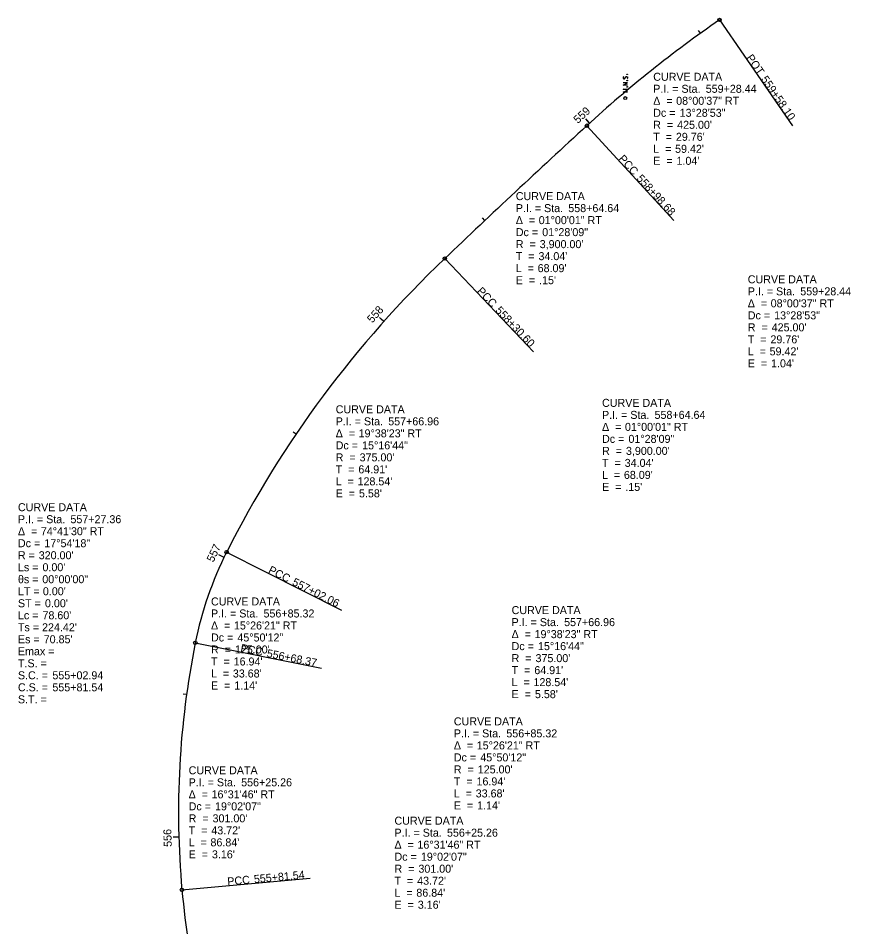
# Model space of a CAD drawing. Extents: x 1922787 to 1923078, y 359089 to 360354.
# Drawn here: x 1922786.9 to 1923078.3, y 360035.7 to 360353.5 of the extents above; entities that cross this region are included whole.
import ezdxf

# ---------------------------------------------------------------- set-up
doc = ezdxf.new("R2010")
doc.units = 0
for name, color, linetype in [('GE_P_Alignment', 7, 'Continuous'), ('GE_P_Alignment_1000_Curve_Data', 7, 'Continuous'), ('GE_P_Alignment_1000_Stations', 7, 'Continuous'), ('GE_P_Alignment_100_Curve_Data', 7, 'Continuous'), ('GE_P_Alignment_100_Stations', 7, 'Continuous'), ('GE_P_Alignment_500_Curve_Data', 7, 'Continuous'), ('GE_P_Alignment_500_Stations', 7, 'Continuous'), ('SV_P_Control_Cells_Set', 7, 'Continuous')]:
    doc.layers.add(name, color=color, linetype=linetype)

msp = doc.modelspace()

# ---------------------------------------------------------------- linework, layer by layer
at = {"layer": 'GE_P_Alignment'}
for centre, radius, start, end in [((1923273.39, 360002.89), 425, 124.5553, 132.5656), ((1925624, 357443.54), 3900, 132.56556, 133.56583), ((1923194.61, 359997.69), 375, 133.5658, 153.2056), ((1922971.45, 360110.39), 125, 153.2056, 168.6447), ((1923144.01, 360075.74), 301, 168.6447, 185.1742), ((1923162.93, 360077.45), 320, 185.1742, 199.2469)]:
    msp.add_arc(centre, radius, start, end, dxfattribs=at)
at = {"layer": 'GE_P_Alignment_1000_Stations'}
for p, q in [((1923032.33, 360352.91), (1923057.86, 360315.85)), ((1922985.91, 360315.9), (1923016.35, 360282.76)), ((1922936.17, 360269.41), (1922967.18, 360236.81)), ((1922859.87, 360166.74), (1922900.04, 360146.45)), ((1922848.9, 360135), (1922893.02, 360126.14)), ((1922844.24, 360048.59), (1922889.05, 360052.65))]:
    msp.add_line(p, q, dxfattribs=at)
for centre in [(1923032.33, 360352.91), (1922985.91, 360315.9), (1922936.17, 360269.41), (1922859.87, 360166.74), (1922848.9, 360135), (1922844.24, 360048.59)]:
    msp.add_circle(centre, 0.6, dxfattribs=at)
at = {"layer": 'GE_P_Alignment_100_Stations'}
for p, q in [((1923032.33, 360352.91), (1923057.86, 360315.85)), ((1923025.7, 360348.25), (1923025, 360349.23)), ((1922986.88, 360316.79), (1922985.53, 360318.27)), ((1922985.91, 360315.9), (1923016.35, 360282.76)), ((1922950.26, 360282.75), (1922949.44, 360283.62)), ((1922936.17, 360269.41), (1922967.18, 360236.81)), ((1922914.88, 360247.44), (1922913.39, 360248.78)), ((1922884.16, 360208.04), (1922883.17, 360208.71)), ((1922858.96, 360164.9), (1922857.16, 360165.77)), ((1922859.87, 360166.74), (1922900.04, 360146.45)), ((1922848.9, 360135), (1922893.02, 360126.14)), ((1922845.83, 360116.89), (1922844.65, 360117.05)), ((1922843.13, 360067.02), (1922841.14, 360066.96)), ((1922844.24, 360048.59), (1922889.05, 360052.65))]:
    msp.add_line(p, q, dxfattribs=at)
for centre in [(1923032.33, 360352.91), (1922985.91, 360315.9), (1922936.17, 360269.41), (1922859.87, 360166.74), (1922848.9, 360135), (1922844.24, 360048.59)]:
    msp.add_circle(centre, 0.6, dxfattribs=at)
at = {"layer": 'GE_P_Alignment_500_Stations'}
for p, q in [((1923032.33, 360352.91), (1923057.86, 360315.85)), ((1922986.88, 360316.79), (1922986.07, 360317.68)), ((1922985.91, 360315.9), (1923016.35, 360282.76)), ((1922936.17, 360269.41), (1922967.18, 360236.81)), ((1922914.88, 360247.44), (1922913.98, 360248.24)), ((1922858.96, 360164.9), (1922857.88, 360165.42)), ((1922859.87, 360166.74), (1922900.04, 360146.45)), ((1922848.9, 360135), (1922893.02, 360126.14)), ((1922843.13, 360067.02), (1922841.94, 360066.99)), ((1922844.24, 360048.59), (1922889.05, 360052.65))]:
    msp.add_line(p, q, dxfattribs=at)
for centre in [(1923032.33, 360352.91), (1922985.91, 360315.9), (1922936.17, 360269.41), (1922859.87, 360166.74), (1922848.9, 360135), (1922844.24, 360048.59)]:
    msp.add_circle(centre, 0.6, dxfattribs=at)
at = {"layer": 'SV_P_Control_Cells_Set'}
for points in [[(1922998.67, 360333.01), (1922998.64, 360332.99), (1922998.62, 360332.96), (1922998.58, 360332.86), (1922998.55, 360332.74), (1922998.55, 360332.65), (1922998.55, 360332.61), (1922998.59, 360332.47), (1922998.67, 360332.35), (1922998.77, 360332.27), (1922998.87, 360332.25), (1922998.94, 360332.25), (1922999.04, 360332.27), (1922999.13, 360332.36), (1922999.51, 360332.97), (1922999.56, 360333.02), (1922999.61, 360333.04), (1922999.69, 360333.07), (1922999.76, 360333.07), (1922999.84, 360333.06), (1922999.89, 360333.04), (1922999.95, 360333.02), (1923000, 360333), (1923000.04, 360332.98), (1923000.08, 360332.95), (1923000.1, 360332.91), (1923000.13, 360332.87), (1923000.14, 360332.84), (1923000.15, 360332.74), (1923000.15, 360332.58), (1923000.13, 360332.48), (1923000.04, 360332.34), (1922999.96, 360332.25)], [(1922999.94, 360333.83), (1922999.94, 360333.88), (1922999.96, 360333.92), (1923000.01, 360333.95), (1923000.08, 360333.95), (1923000.13, 360333.92), (1923000.15, 360333.88), (1923000.15, 360333.83), (1923000.13, 360333.79), (1923000.08, 360333.76), (1923000.01, 360333.76), (1922999.96, 360333.79), (1922999.94, 360333.83)], [(1923000.15, 360330.04), (1922998.55, 360330.04), (1923000.15, 360330.86), (1922998.55, 360330.86)], [(1922999.94, 360331.64), (1922999.94, 360331.7), (1922999.96, 360331.73), (1923000.01, 360331.77), (1923000.08, 360331.77), (1923000.13, 360331.73), (1923000.15, 360331.7), (1923000.15, 360331.64), (1923000.13, 360331.61), (1923000.08, 360331.58), (1923000.01, 360331.58), (1922999.96, 360331.61), (1922999.94, 360331.64)], [(1922999.94, 360329.43), (1922999.94, 360329.48), (1922999.96, 360329.52), (1923000.01, 360329.55), (1923000.08, 360329.55), (1923000.13, 360329.52), (1923000.15, 360329.48), (1923000.15, 360329.43), (1923000.13, 360329.4), (1923000.08, 360329.36), (1923000.01, 360329.36), (1922999.96, 360329.4), (1922999.94, 360329.43)], [(1923000.15, 360327.67), (1922998.55, 360327.67), (1923000.15, 360328.17), (1922998.55, 360328.66), (1923000.15, 360328.66)]]:
    msp.add_lwpolyline(points, dxfattribs=at)
msp.add_circle((1922999.35, 360325.58), 0.497, dxfattribs=at)

# ---------------------------------------------------------------- texts
at = {"layer": 'GE_P_Alignment_1000_Curve_Data'}
for s, p in [('CURVE DATA', (1923009.12, 360331.61)), ('P.I. = Sta. ', (1923009.12, 360327.41)), ('559+28.44', (1923027.49, 360327.41)), ('Δ  = ', (1923009.12, 360323.21)), ('08°00\'37" RT', (1923017.14, 360323.21)), ('Dc = ', (1923009.12, 360319.01)), ('13°28\'53"', (1923018.36, 360319.01)), ('R  = ', (1923009.12, 360314.81)), ("425.00'", (1923017.49, 360314.81)), ('T  = ', (1923009.12, 360310.61)), ("29.76'", (1923017.05, 360310.61)), ('L  = ', (1923009.12, 360306.41)), ("59.42'", (1923016.77, 360306.41)), ('E  = ', (1923009.12, 360302.21)), ("1.04'", (1923017.27, 360302.21)), ('CURVE DATA', (1922961.04, 360289.86)), ('P.I. = Sta. ', (1922961.04, 360285.66)), ('558+64.64', (1922979.41, 360285.66)), ('Δ  = ', (1922961.04, 360281.46)), ('01°00\'01" RT', (1922969.06, 360281.46)), ('Dc = ', (1922961.04, 360277.26)), ('01°28\'09"', (1922970.28, 360277.26)), ('R  = ', (1922961.04, 360273.06)), ("3,900.00'", (1922969.4, 360273.06)), ('T  = ', (1922961.04, 360268.86)), ("34.04'", (1922968.97, 360268.86)), ('L  = ', (1922961.04, 360264.66)), ("68.09'", (1922968.68, 360264.66)), ('E  = ', (1922961.04, 360260.46)), (".15'", (1922969.19, 360260.46)), ('CURVE DATA', (1922898.02, 360215.28)), ('P.I. = Sta. ', (1922898.02, 360211.08)), ('557+66.96', (1922916.39, 360211.08)), ('Δ  = ', (1922898.02, 360206.88)), ('19°38\'23" RT', (1922906.04, 360206.88)), ('Dc = ', (1922898.02, 360202.68)), ('15°16\'44"', (1922907.26, 360202.68)), ('R  = ', (1922898.02, 360198.48)), ("375.00'", (1922906.39, 360198.48)), ('T  = ', (1922898.02, 360194.28)), ("64.91'", (1922905.95, 360194.28)), ('L  = ', (1922898.02, 360190.08)), ("128.54'", (1922905.67, 360190.08)), ('E  = ', (1922898.02, 360185.88)), ("5.58'", (1922906.17, 360185.88)), ('CURVE DATA', (1922786.84, 360181.04)), ('P.I. = Sta. ', (1922786.84, 360176.84)), ('557+27.36', (1922805.21, 360176.84)), ('Δ  = ', (1922786.84, 360172.64)), ('74°41\'30" RT', (1922794.86, 360172.64)), ('Dc = ', (1922786.84, 360168.44)), ('17°54\'18"', (1922796.08, 360168.44)), ('R = ', (1922786.84, 360164.24)), ("320.00'", (1922794.12, 360164.24)), ('Ls = ', (1922786.84, 360160.04)), ("0.00'", (1922795.43, 360160.04)), ('θs = ', (1922786.84, 360155.84)), ('00°00\'00"', (1922795.37, 360155.84)), ('LT = ', (1922786.84, 360151.64)), ("0.00'", (1922795.57, 360151.64)), ('ST = ', (1922786.84, 360147.44)), ("0.00'", (1922796.3, 360147.44)), ('CURVE DATA', (1922854.39, 360148.07)), ('Lc = ', (1922786.84, 360143.24)), ("78.60'", (1922795.43, 360143.24)), ('P.I. = Sta. ', (1922854.39, 360143.87)), ('556+85.32', (1922872.76, 360143.87)), ('Ts = ', (1922786.84, 360139.04)), ("224.42'", (1922795.28, 360139.04)), ('Δ  = ', (1922854.39, 360139.67)), ('15°26\'21" RT', (1922862.41, 360139.67)), ('Es = ', (1922786.84, 360134.84)), ("70.85'", (1922795.86, 360134.84)), ('Dc = ', (1922854.39, 360135.47)), ('45°50\'12"', (1922863.63, 360135.47)), ('Emax = ', (1922786.84, 360130.64)), ('R  = ', (1922854.39, 360131.27)), ("125.00'", (1922862.76, 360131.27)), ('T.S. = ', (1922786.84, 360126.44)), ('T  = ', (1922854.39, 360127.07)), ("16.94'", (1922862.32, 360127.07)), ("33.68'", (1922862.03, 360122.87)), ('S.C. = ', (1922786.84, 360122.24)), ('555+02.94', (1922798.9, 360122.24)), ('L  = ', (1922854.39, 360122.87)), ('C.S. = ', (1922786.84, 360118.04)), ('555+81.54', (1922798.9, 360118.04)), ('E  = ', (1922854.39, 360118.67)), ("1.14'", (1922862.54, 360118.67)), ('S.T. = ', (1922786.84, 360113.84)), ('CURVE DATA', (1922846.57, 360089)), ('P.I. = Sta. ', (1922846.57, 360084.8)), ('556+25.26', (1922864.94, 360084.8)), ('Δ  = ', (1922846.57, 360080.6)), ('16°31\'46" RT', (1922854.59, 360080.6)), ('Dc = ', (1922846.57, 360076.4)), ('19°02\'07"', (1922855.81, 360076.4)), ('R  = ', (1922846.57, 360072.2)), ("301.00'", (1922854.94, 360072.2)), ('T  = ', (1922846.57, 360068)), ("43.72'", (1922854.5, 360068)), ('L  = ', (1922846.57, 360063.8)), ("86.84'", (1922854.21, 360063.8)), ('E  = ', (1922846.57, 360059.6)), ("3.16'", (1922854.72, 360059.6))]:
    msp.add_text(s, height=2.8, dxfattribs=at).set_placement(p)
at = {"layer": 'GE_P_Alignment_1000_Stations'}
for s, rotation, p in [('POT', 304.5553, (1923041.51, 360339.66)), ('559+58.10', 304.5553, (1923046.69, 360332.14)), ('PCC', 312.5656, (1922996.77, 360304.14)), ('558+98.68', 312.5656, (1923003.1, 360297.26)), ('PCC', 313.5658, (1922947.23, 360257.84)), ('558+30.60', 313.5658, (1922953.68, 360251.07)), ('PCC', 333.2056, (1922874.18, 360159.57)), ('557+02.06', 333.2056, (1922882.53, 360155.35)), ('PCC', 348.6447, (1922864.55, 360131.91)), ('556+68.37', 348.6447, (1922873.72, 360130.07)), ('PCC', 5.1742, (1922860.22, 360050.09)), ('555+81.54', 5.1742, (1922869.53, 360050.93))]:
    msp.add_text(s, height=2.8, rotation=rotation, dxfattribs=at).set_placement(p)
at = {"layer": 'GE_P_Alignment_100_Curve_Data'}
for s, p in [('CURVE DATA', (1923042.2, 360260.76)), ('P.I. = Sta. ', (1923042.2, 360256.56)), ('559+28.44', (1923060.56, 360256.56)), ('Δ  = ', (1923042.2, 360252.36)), ('08°00\'37" RT', (1923050.22, 360252.36)), ('Dc = ', (1923042.2, 360248.16)), ('13°28\'53"', (1923051.43, 360248.16)), ('R  = ', (1923042.2, 360243.96)), ("425.00'", (1923050.56, 360243.96)), ('T  = ', (1923042.2, 360239.76)), ("29.76'", (1923050.13, 360239.76)), ('L  = ', (1923042.2, 360235.56)), ("59.42'", (1923049.84, 360235.56)), ('E  = ', (1923042.2, 360231.36)), ("1.04'", (1923050.35, 360231.36)), ('CURVE DATA', (1922991.21, 360217.54)), ('P.I. = Sta. ', (1922991.21, 360213.34)), ('558+64.64', (1923009.58, 360213.34)), ('Δ  = ', (1922991.21, 360209.14)), ('01°00\'01" RT', (1922999.23, 360209.14)), ('Dc = ', (1922991.21, 360204.94)), ('01°28\'09"', (1923000.45, 360204.94)), ('R  = ', (1922991.21, 360200.74)), ("3,900.00'", (1922999.58, 360200.74)), ('T  = ', (1922991.21, 360196.54)), ("34.04'", (1922999.14, 360196.54)), ('L  = ', (1922991.21, 360192.34)), ("68.09'", (1922998.86, 360192.34)), ('E  = ', (1922991.21, 360188.14)), (".15'", (1922999.36, 360188.14)), ('CURVE DATA', (1922786.84, 360181.04)), ('P.I. = Sta. ', (1922786.84, 360176.84)), ('557+27.36', (1922805.21, 360176.84)), ('Δ  = ', (1922786.84, 360172.64)), ('74°41\'30" RT', (1922794.86, 360172.64)), ('Dc = ', (1922786.84, 360168.44)), ('17°54\'18"', (1922796.08, 360168.44)), ('R = ', (1922786.84, 360164.24)), ("320.00'", (1922794.12, 360164.24)), ('Ls = ', (1922786.84, 360160.04)), ("0.00'", (1922795.43, 360160.04)), ('θs = ', (1922786.84, 360155.84)), ('00°00\'00"', (1922795.37, 360155.84)), ('LT = ', (1922786.84, 360151.64)), ("0.00'", (1922795.57, 360151.64)), ('ST = ', (1922786.84, 360147.44)), ("0.00'", (1922796.3, 360147.44)), ('Lc = ', (1922786.84, 360143.24)), ("78.60'", (1922795.43, 360143.24)), ('CURVE DATA', (1922959.57, 360145.04)), ('Ts = ', (1922786.84, 360139.04)), ("224.42'", (1922795.28, 360139.04)), ('P.I. = Sta. ', (1922959.57, 360140.84)), ('557+66.96', (1922977.94, 360140.84)), ('Δ  = ', (1922959.57, 360136.64)), ('19°38\'23" RT', (1922967.6, 360136.64)), ('Es = ', (1922786.84, 360134.84)), ("70.85'", (1922795.86, 360134.84)), ('Dc = ', (1922959.57, 360132.44)), ('15°16\'44"', (1922968.81, 360132.44)), ('Emax = ', (1922786.84, 360130.64)), ('T.S. = ', (1922786.84, 360126.44)), ('R  = ', (1922959.57, 360128.24)), ("375.00'", (1922967.94, 360128.24)), ('T  = ', (1922959.57, 360124.04)), ("64.91'", (1922967.51, 360124.04)), ('S.C. = ', (1922786.84, 360122.24)), ('555+02.94', (1922798.9, 360122.24)), ('L  = ', (1922959.57, 360119.84)), ("128.54'", (1922967.22, 360119.84)), ('C.S. = ', (1922786.84, 360118.04)), ('555+81.54', (1922798.9, 360118.04)), ('S.T. = ', (1922786.84, 360113.84)), ('E  = ', (1922959.57, 360115.64)), ("5.58'", (1922967.73, 360115.64)), ('CURVE DATA', (1922939.36, 360106.12)), ('P.I. = Sta. ', (1922939.36, 360101.92)), ('556+85.32', (1922957.73, 360101.92)), ('Δ  = ', (1922939.36, 360097.72)), ('15°26\'21" RT', (1922947.38, 360097.72)), ('Dc = ', (1922939.36, 360093.52)), ('45°50\'12"', (1922948.6, 360093.52)), ('R  = ', (1922939.36, 360089.32)), ("125.00'", (1922947.73, 360089.32)), ('T  = ', (1922939.36, 360085.12)), ("16.94'", (1922947.29, 360085.12)), ('L  = ', (1922939.36, 360080.92)), ("33.68'", (1922947.01, 360080.92)), ('E  = ', (1922939.36, 360076.72)), ("1.14'", (1922947.51, 360076.72)), ('CURVE DATA', (1922918.59, 360071.38)), ('P.I. = Sta. ', (1922918.59, 360067.18)), ('556+25.26', (1922936.96, 360067.18)), ('Δ  = ', (1922918.59, 360062.98)), ('16°31\'46" RT', (1922926.62, 360062.98)), ('Dc = ', (1922918.59, 360058.78)), ('19°02\'07"', (1922927.83, 360058.78)), ('R  = ', (1922918.59, 360054.58)), ("301.00'", (1922926.96, 360054.58)), ('T  = ', (1922918.59, 360050.38)), ("43.72'", (1922926.53, 360050.38)), ('L  = ', (1922918.59, 360046.18)), ("86.84'", (1922926.24, 360046.18)), ('E  = ', (1922918.59, 360041.98)), ("3.16'", (1922926.75, 360041.98))]:
    msp.add_text(s, height=2.8, dxfattribs=at).set_placement(p)
at = {"layer": 'GE_P_Alignment_100_Stations'}
for s, rotation, p in [('POT', 304.5553, (1923041.51, 360339.66)), ('559+58.10', 304.5553, (1923046.69, 360332.14)), ('559', 42.3881, (1922982.76, 360316.48)), ('PCC', 312.5656, (1922996.77, 360304.14)), ('558+98.68', 312.5656, (1923003.1, 360297.26)), ('PCC', 313.5658, (1922947.23, 360257.84)), ('558', 48.2407, (1922910.8, 360246.69)), ('558+30.60', 313.5658, (1922953.68, 360251.07)), ('557', 64.1477, (1922855.22, 360163)), ('PCC', 333.2056, (1922874.18, 360159.57)), ('557+02.06', 333.2056, (1922882.53, 360155.35)), ('PCC', 348.6447, (1922864.55, 360131.91)), ('556+68.37', 348.6447, (1922873.72, 360130.07)), ('556', 91.6595, (1922840.68, 360063.66)), ('PCC', 5.1742, (1922860.22, 360050.09)), ('555+81.54', 5.1742, (1922869.53, 360050.93))]:
    msp.add_text(s, height=2.8, rotation=rotation, dxfattribs=at).set_placement(p)
at = {"layer": 'GE_P_Alignment_500_Curve_Data'}
for s, p in [('CURVE DATA', (1923009.12, 360331.61)), ('P.I. = Sta. ', (1923009.12, 360327.41)), ('559+28.44', (1923027.49, 360327.41)), ('Δ  = ', (1923009.12, 360323.21)), ('08°00\'37" RT', (1923017.14, 360323.21)), ('Dc = ', (1923009.12, 360319.01)), ('13°28\'53"', (1923018.36, 360319.01)), ('R  = ', (1923009.12, 360314.81)), ("425.00'", (1923017.49, 360314.81)), ('T  = ', (1923009.12, 360310.61)), ("29.76'", (1923017.05, 360310.61)), ('L  = ', (1923009.12, 360306.41)), ("59.42'", (1923016.77, 360306.41)), ('E  = ', (1923009.12, 360302.21)), ("1.04'", (1923017.27, 360302.21)), ('CURVE DATA', (1922961.04, 360289.86)), ('P.I. = Sta. ', (1922961.04, 360285.66)), ('558+64.64', (1922979.41, 360285.66)), ('Δ  = ', (1922961.04, 360281.46)), ('01°00\'01" RT', (1922969.06, 360281.46)), ('Dc = ', (1922961.04, 360277.26)), ('01°28\'09"', (1922970.28, 360277.26)), ('R  = ', (1922961.04, 360273.06)), ("3,900.00'", (1922969.4, 360273.06)), ('T  = ', (1922961.04, 360268.86)), ("34.04'", (1922968.97, 360268.86)), ('L  = ', (1922961.04, 360264.66)), ("68.09'", (1922968.68, 360264.66)), ('E  = ', (1922961.04, 360260.46)), (".15'", (1922969.19, 360260.46)), ('CURVE DATA', (1922898.02, 360215.28)), ('P.I. = Sta. ', (1922898.02, 360211.08)), ('557+66.96', (1922916.39, 360211.08)), ('Δ  = ', (1922898.02, 360206.88)), ('19°38\'23" RT', (1922906.04, 360206.88)), ('Dc = ', (1922898.02, 360202.68)), ('15°16\'44"', (1922907.26, 360202.68)), ('R  = ', (1922898.02, 360198.48)), ("375.00'", (1922906.39, 360198.48)), ('T  = ', (1922898.02, 360194.28)), ("64.91'", (1922905.95, 360194.28)), ('L  = ', (1922898.02, 360190.08)), ("128.54'", (1922905.67, 360190.08)), ('E  = ', (1922898.02, 360185.88)), ("5.58'", (1922906.17, 360185.88)), ('CURVE DATA', (1922786.84, 360181.04)), ('P.I. = Sta. ', (1922786.84, 360176.84)), ('557+27.36', (1922805.21, 360176.84)), ('Δ  = ', (1922786.84, 360172.64)), ('74°41\'30" RT', (1922794.86, 360172.64)), ('Dc = ', (1922786.84, 360168.44)), ('17°54\'18"', (1922796.08, 360168.44)), ('R = ', (1922786.84, 360164.24)), ("320.00'", (1922794.12, 360164.24)), ('Ls = ', (1922786.84, 360160.04)), ("0.00'", (1922795.43, 360160.04)), ('θs = ', (1922786.84, 360155.84)), ('00°00\'00"', (1922795.37, 360155.84)), ('LT = ', (1922786.84, 360151.64)), ("0.00'", (1922795.57, 360151.64)), ('ST = ', (1922786.84, 360147.44)), ("0.00'", (1922796.3, 360147.44)), ('CURVE DATA', (1922854.39, 360148.07)), ('Lc = ', (1922786.84, 360143.24)), ("78.60'", (1922795.43, 360143.24)), ('P.I. = Sta. ', (1922854.39, 360143.87)), ('556+85.32', (1922872.76, 360143.87)), ('Ts = ', (1922786.84, 360139.04)), ("224.42'", (1922795.28, 360139.04)), ('Δ  = ', (1922854.39, 360139.67)), ('15°26\'21" RT', (1922862.41, 360139.67)), ('Es = ', (1922786.84, 360134.84)), ("70.85'", (1922795.86, 360134.84)), ('Dc = ', (1922854.39, 360135.47)), ('45°50\'12"', (1922863.63, 360135.47)), ('Emax = ', (1922786.84, 360130.64)), ('R  = ', (1922854.39, 360131.27)), ("125.00'", (1922862.76, 360131.27)), ('T.S. = ', (1922786.84, 360126.44)), ('T  = ', (1922854.39, 360127.07)), ("16.94'", (1922862.32, 360127.07)), ("33.68'", (1922862.03, 360122.87)), ('S.C. = ', (1922786.84, 360122.24)), ('555+02.94', (1922798.9, 360122.24)), ('L  = ', (1922854.39, 360122.87)), ('C.S. = ', (1922786.84, 360118.04)), ('555+81.54', (1922798.9, 360118.04)), ('E  = ', (1922854.39, 360118.67)), ("1.14'", (1922862.54, 360118.67)), ('S.T. = ', (1922786.84, 360113.84)), ('CURVE DATA', (1922846.57, 360089)), ('P.I. = Sta. ', (1922846.57, 360084.8)), ('556+25.26', (1922864.94, 360084.8)), ('Δ  = ', (1922846.57, 360080.6)), ('16°31\'46" RT', (1922854.59, 360080.6)), ('Dc = ', (1922846.57, 360076.4)), ('19°02\'07"', (1922855.81, 360076.4)), ('R  = ', (1922846.57, 360072.2)), ("301.00'", (1922854.94, 360072.2)), ('T  = ', (1922846.57, 360068)), ("43.72'", (1922854.5, 360068)), ('L  = ', (1922846.57, 360063.8)), ("86.84'", (1922854.21, 360063.8)), ('E  = ', (1922846.57, 360059.6)), ("3.16'", (1922854.72, 360059.6))]:
    msp.add_text(s, height=2.8, dxfattribs=at).set_placement(p)
at = {"layer": 'GE_P_Alignment_500_Stations'}
for s, rotation, p in [('POT', 304.5553, (1923041.51, 360339.66)), ('559+58.10', 304.5553, (1923046.69, 360332.14)), ('PCC', 312.5656, (1922996.77, 360304.14)), ('558+98.68', 312.5656, (1923003.1, 360297.26)), ('PCC', 313.5658, (1922947.23, 360257.84)), ('558+30.60', 313.5658, (1922953.68, 360251.07)), ('PCC', 333.2056, (1922874.18, 360159.57)), ('557+02.06', 333.2056, (1922882.53, 360155.35)), ('PCC', 348.6447, (1922864.55, 360131.91)), ('556+68.37', 348.6447, (1922873.72, 360130.07)), ('PCC', 5.1742, (1922860.22, 360050.09)), ('555+81.54', 5.1742, (1922869.53, 360050.93))]:
    msp.add_text(s, height=2.8, rotation=rotation, dxfattribs=at).set_placement(p)

doc.saveas('drawing.dxf')
